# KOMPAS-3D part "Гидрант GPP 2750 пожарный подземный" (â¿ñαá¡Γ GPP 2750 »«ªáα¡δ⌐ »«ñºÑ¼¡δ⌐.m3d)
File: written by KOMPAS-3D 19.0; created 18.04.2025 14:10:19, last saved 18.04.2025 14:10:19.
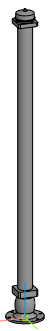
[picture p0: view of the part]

Document properties: Полное имя файла: E:\Dendor Работа Сачек\3D для проекитирвщиков\11.1 Тип GPP. Гидрант пожарный подземный\stp_Тип GPP. 750-6000 Гидрант пожарный подземный\Гидрант GPP 2750 пожарный подземный.m3d

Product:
- Part/product: Гидрант GPP 2750 пожарный подземный

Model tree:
1. Операция без истории:1  (labels: Гидрант GPP 2750 пожарный подземный)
